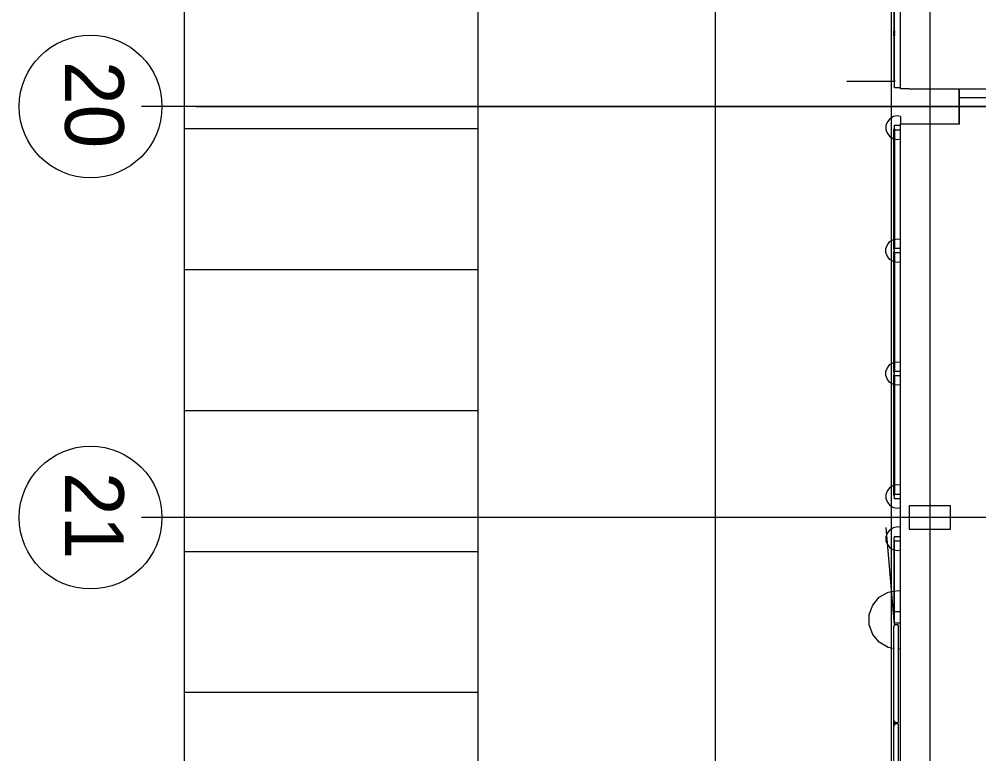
# Model space of a CAD drawing. Extents: x -264165 to -263575, y -1242333 to -1242036.
# Drawn here: x -263923.9 to -263907.56, y -1242220.9 to -1242208.39 of the extents above; entities that cross this region are included whole.
import ezdxf

# ---------------------------------------------------------------- set-up
doc = ezdxf.new("R2010")
doc.units = 0
doc.layers.add('KFA_HESCON_OSI_STAVBY', color=7, linetype='Continuous')
doc.layers.add('KFA_SITUACIA_DRS_VYTYCOVAK_SEDA', color=7, linetype='Continuous')

msp = doc.modelspace()

# ---------------------------------------------------------------- linework, layer by layer
at = {"layer": 'KFA_HESCON_OSI_STAVBY'}
for p, q in [((-263908.393, -1242080.447), (-263908.393, -1242248.737)), ((-263787.486, -1242209.882), (-263921.823, -1242209.882)), ((-263920.885, -1242209.882), (-263905.505, -1242209.882)), ((-263787.486, -1242216.882), (-263921.823, -1242216.882))]:
    msp.add_line(p, q, dxfattribs=at)
for centre in [(-263922.688, -1242209.882), (-263922.688, -1242216.882)]:
    msp.add_circle(centre, 1.216, dxfattribs=at)
at = {"layer": 'KFA_SITUACIA_DRS_VYTYCOVAK_SEDA'}
for p, q in [((-263921.093, -1242087.308), (-263921.093, -1242241.458)), ((-263912.043, -1242228.625), (-263912.043, -1242100.14)), ((-263916.093, -1242187.557), (-263916.093, -1242241.458)), ((-263909.043, -1242227.382), (-263909.043, -1242196.333)), ((-263908.893, -1242209.582), (-263908.893, -1242203.182)), ((-263908.893, -1242209.582), (-263908.893, -1242203.182)), ((-263908.993, -1242209.562), (-263908.993, -1242207.702)), ((-263908.993, -1242209.562), (-263908.993, -1242207.702)), ((-263909.003, -1242207.833), (-263909.003, -1242208.592)), ((-263909.003, -1242207.833), (-263909.003, -1242208.592)), ((-263909.003, -1242208.592), (-263908.993, -1242208.592)), ((-263909.003, -1242208.592), (-263908.993, -1242208.592)), ((-263909.003, -1242208.672), (-263909.003, -1242208.592)), ((-263909.003, -1242208.672), (-263909.003, -1242208.592)), ((-263909.003, -1242208.592), (-263908.993, -1242208.592)), ((-263909.003, -1242208.592), (-263908.993, -1242208.592)), ((-263908.993, -1242208.592), (-263908.993, -1242208.622)), ((-263908.993, -1242208.592), (-263908.993, -1242208.622)), ((-263908.993, -1242208.672), (-263909.003, -1242208.672)), ((-263908.993, -1242208.672), (-263909.003, -1242208.672)), ((-263909.003, -1242208.673), (-263909.003, -1242209.432)), ((-263909.003, -1242208.673), (-263909.003, -1242209.432)), ((-263908.993, -1242208.673), (-263909.003, -1242208.673)), ((-263908.993, -1242208.673), (-263909.003, -1242208.673)), ((-263908.993, -1242208.642), (-263908.993, -1242208.673)), ((-263908.993, -1242208.642), (-263908.993, -1242208.673)), ((-263908.993, -1242209.457), (-263909.808, -1242209.457)), ((-263908.993, -1242209.457), (-263909.808, -1242209.457)), ((-263908.993, -1242209.432), (-263909.003, -1242209.432)), ((-263908.993, -1242209.432), (-263909.003, -1242209.432)), ((-263908.993, -1242209.432), (-263908.993, -1242209.457)), ((-263908.993, -1242209.432), (-263908.993, -1242209.457)), ((-263908.893, -1242209.562), (-263908.993, -1242209.562)), ((-263908.893, -1242209.562), (-263908.993, -1242209.562)), ((-263908.893, -1242209.562), (-263908.893, -1242209.582)), ((-263908.893, -1242209.562), (-263908.893, -1242209.582)), ((-263908.743, -1242209.582), (-263908.893, -1242209.582)), ((-263908.743, -1242209.582), (-263908.893, -1242209.582)), ((-263908.743, -1242209.582), (-263907.893, -1242209.582)), ((-263908.743, -1242209.582), (-263907.893, -1242209.582)), ((-263907.893, -1242210.182), (-263907.893, -1242209.582)), ((-263907.893, -1242210.182), (-263907.893, -1242209.582)), ((-263907.893, -1242209.582), (-263907.893, -1242209.732)), ((-263907.893, -1242209.582), (-263907.893, -1242209.732)), ((-263907.893, -1242209.582), (-263907.368, -1242209.582)), ((-263907.893, -1242209.582), (-263907.368, -1242209.582)), ((-263907.893, -1242209.732), (-263907.893, -1242210.182)), ((-263907.893, -1242209.732), (-263907.893, -1242210.182)), ((-263907.368, -1242209.732), (-263907.893, -1242209.732)), ((-263907.368, -1242209.732), (-263907.893, -1242209.732)), ((-263907.368, -1242209.732), (-263907.893, -1242209.732)), ((-263907.368, -1242209.732), (-263907.893, -1242209.732)), ((-263909.011, -1242210.054), (-263909.071, -1242210.089)), ((-263909.011, -1242210.054), (-263909.071, -1242210.089)), ((-263908.943, -1242210.042), (-263909.011, -1242210.054)), ((-263908.943, -1242210.042), (-263909.011, -1242210.054)), ((-263908.893, -1242210.051), (-263908.943, -1242210.042)), ((-263908.893, -1242210.051), (-263908.943, -1242210.042)), ((-263908.893, -1242210.051), (-263908.893, -1242210.182)), ((-263908.893, -1242210.051), (-263908.893, -1242210.182)), ((-263909.116, -1242210.142), (-263909.14, -1242210.207)), ((-263909.116, -1242210.142), (-263909.14, -1242210.207)), ((-263909.14, -1242210.207), (-263909.14, -1242210.277)), ((-263909.14, -1242210.207), (-263909.14, -1242210.277)), ((-263909.071, -1242210.089), (-263909.116, -1242210.142)), ((-263909.071, -1242210.089), (-263909.116, -1242210.142)), ((-263908.993, -1242210.282), (-263908.993, -1242210.202)), ((-263908.993, -1242210.282), (-263908.993, -1242210.202)), ((-263908.993, -1242210.202), (-263908.893, -1242210.202)), ((-263908.993, -1242210.202), (-263908.893, -1242210.202)), ((-263908.893, -1242216.882), (-263908.893, -1242210.182)), ((-263908.893, -1242216.882), (-263908.893, -1242210.182)), ((-263908.893, -1242216.882), (-263908.893, -1242210.182)), ((-263908.893, -1242216.882), (-263908.893, -1242210.182)), ((-263907.893, -1242210.182), (-263908.893, -1242210.182)), ((-263907.893, -1242210.182), (-263908.893, -1242210.182)), ((-263921.093, -1242210.257), (-263916.093, -1242210.257)), ((-263909.14, -1242210.277), (-263909.116, -1242210.342)), ((-263909.14, -1242210.277), (-263909.116, -1242210.342)), ((-263909.116, -1242210.342), (-263909.071, -1242210.395)), ((-263909.116, -1242210.342), (-263909.071, -1242210.395)), ((-263909.071, -1242210.395), (-263909.011, -1242210.43)), ((-263909.071, -1242210.395), (-263909.011, -1242210.43)), ((-263909.003, -1242212.318), (-263909.003, -1242210.259)), ((-263909.003, -1242212.318), (-263909.003, -1242210.259)), ((-263909.003, -1242210.259), (-263908.993, -1242210.259)), ((-263909.003, -1242210.259), (-263908.993, -1242210.259)), ((-263908.993, -1242210.259), (-263908.993, -1242212.296)), ((-263908.993, -1242210.259), (-263908.993, -1242212.296)), ((-263908.893, -1242210.282), (-263908.993, -1242210.282)), ((-263908.893, -1242210.282), (-263908.993, -1242210.282)), ((-263909.011, -1242210.43), (-263909.003, -1242210.432)), ((-263909.011, -1242210.43), (-263909.003, -1242210.432)), ((-263908.993, -1242210.433), (-263908.943, -1242210.442)), ((-263908.993, -1242210.433), (-263908.943, -1242210.442)), ((-263908.943, -1242210.442), (-263908.893, -1242210.433)), ((-263908.943, -1242210.442), (-263908.893, -1242210.433)), ((-263909.116, -1242212.236), (-263909.071, -1242212.182)), ((-263909.116, -1242212.236), (-263909.071, -1242212.182)), ((-263909.071, -1242212.182), (-263909.011, -1242212.148)), ((-263909.071, -1242212.182), (-263909.011, -1242212.148)), ((-263909.011, -1242212.148), (-263909.003, -1242212.146)), ((-263909.011, -1242212.148), (-263909.003, -1242212.146)), ((-263908.993, -1242212.144), (-263908.943, -1242212.136)), ((-263908.993, -1242212.144), (-263908.943, -1242212.136)), ((-263908.943, -1242212.136), (-263908.893, -1242212.144)), ((-263908.943, -1242212.136), (-263908.893, -1242212.144)), ((-263909.14, -1242212.301), (-263909.116, -1242212.236)), ((-263909.14, -1242212.301), (-263909.116, -1242212.236)), ((-263909.14, -1242212.37), (-263909.14, -1242212.301)), ((-263909.14, -1242212.37), (-263909.14, -1242212.301)), ((-263909.003, -1242212.318), (-263908.993, -1242212.318)), ((-263909.003, -1242212.318), (-263908.993, -1242212.318)), ((-263909.003, -1242214.412), (-263909.003, -1242212.353)), ((-263909.003, -1242214.412), (-263909.003, -1242212.353)), ((-263909.003, -1242212.353), (-263908.993, -1242212.353)), ((-263909.003, -1242212.353), (-263908.993, -1242212.353)), ((-263908.993, -1242212.296), (-263908.893, -1242212.296)), ((-263908.993, -1242212.296), (-263908.893, -1242212.296)), ((-263908.993, -1242212.353), (-263908.993, -1242212.318)), ((-263908.993, -1242212.353), (-263908.993, -1242212.318)), ((-263909.116, -1242212.436), (-263909.14, -1242212.37)), ((-263909.116, -1242212.436), (-263909.14, -1242212.37)), ((-263909.071, -1242212.489), (-263909.116, -1242212.436)), ((-263909.071, -1242212.489), (-263909.116, -1242212.436)), ((-263909.011, -1242212.523), (-263909.071, -1242212.489)), ((-263909.011, -1242212.523), (-263909.071, -1242212.489)), ((-263909.003, -1242212.525), (-263909.011, -1242212.523)), ((-263909.003, -1242212.525), (-263909.011, -1242212.523)), ((-263908.993, -1242212.376), (-263908.993, -1242214.389)), ((-263908.993, -1242212.376), (-263908.993, -1242214.389)), ((-263908.893, -1242212.376), (-263908.993, -1242212.376)), ((-263908.893, -1242212.376), (-263908.993, -1242212.376)), ((-263908.943, -1242212.536), (-263908.993, -1242212.527)), ((-263908.943, -1242212.536), (-263908.993, -1242212.527)), ((-263908.893, -1242212.527), (-263908.943, -1242212.536)), ((-263908.893, -1242212.527), (-263908.943, -1242212.536)), ((-263921.093, -1242212.657), (-263916.093, -1242212.657)), ((-263909.14, -1242214.394), (-263909.116, -1242214.329)), ((-263909.14, -1242214.394), (-263909.116, -1242214.329)), ((-263909.116, -1242214.329), (-263909.071, -1242214.276)), ((-263909.116, -1242214.329), (-263909.071, -1242214.276)), ((-263909.071, -1242214.276), (-263909.011, -1242214.241)), ((-263909.071, -1242214.276), (-263909.011, -1242214.241)), ((-263909.011, -1242214.241), (-263909.003, -1242214.239)), ((-263909.011, -1242214.241), (-263909.003, -1242214.239)), ((-263908.993, -1242214.238), (-263908.943, -1242214.229)), ((-263908.993, -1242214.238), (-263908.943, -1242214.229)), ((-263908.943, -1242214.229), (-263908.893, -1242214.238)), ((-263908.943, -1242214.229), (-263908.893, -1242214.238)), ((-263909.14, -1242214.464), (-263909.14, -1242214.394)), ((-263909.14, -1242214.464), (-263909.14, -1242214.394)), ((-263909.116, -1242214.529), (-263909.14, -1242214.464)), ((-263909.116, -1242214.529), (-263909.14, -1242214.464)), ((-263909.003, -1242214.412), (-263908.993, -1242214.412)), ((-263909.003, -1242214.412), (-263908.993, -1242214.412)), ((-263909.003, -1242216.505), (-263909.003, -1242214.446)), ((-263909.003, -1242216.505), (-263909.003, -1242214.446)), ((-263909.003, -1242214.446), (-263908.993, -1242214.446)), ((-263909.003, -1242214.446), (-263908.993, -1242214.446)), ((-263908.993, -1242214.389), (-263908.893, -1242214.389)), ((-263908.993, -1242214.389), (-263908.893, -1242214.389)), ((-263908.993, -1242214.446), (-263908.993, -1242214.412)), ((-263908.993, -1242214.446), (-263908.993, -1242214.412)), ((-263908.993, -1242214.469), (-263908.993, -1242216.482)), ((-263908.993, -1242214.469), (-263908.993, -1242216.482)), ((-263908.893, -1242214.469), (-263908.993, -1242214.469)), ((-263908.893, -1242214.469), (-263908.993, -1242214.469)), ((-263909.071, -1242214.582), (-263909.116, -1242214.529)), ((-263909.071, -1242214.582), (-263909.116, -1242214.529)), ((-263909.011, -1242214.617), (-263909.071, -1242214.582)), ((-263909.011, -1242214.617), (-263909.071, -1242214.582)), ((-263909.003, -1242214.618), (-263909.011, -1242214.617)), ((-263909.003, -1242214.618), (-263909.011, -1242214.617)), ((-263908.943, -1242214.629), (-263908.993, -1242214.62)), ((-263908.943, -1242214.629), (-263908.993, -1242214.62)), ((-263908.893, -1242214.62), (-263908.943, -1242214.629)), ((-263908.893, -1242214.62), (-263908.943, -1242214.629)), ((-263921.093, -1242215.057), (-263916.093, -1242215.057)), ((-263909.116, -1242216.422), (-263909.14, -1242216.487)), ((-263909.116, -1242216.422), (-263909.14, -1242216.487)), ((-263909.071, -1242216.369), (-263909.116, -1242216.422)), ((-263909.071, -1242216.369), (-263909.116, -1242216.422)), ((-263909.011, -1242216.334), (-263909.071, -1242216.369)), ((-263909.011, -1242216.334), (-263909.071, -1242216.369)), ((-263909.003, -1242216.333), (-263909.011, -1242216.334)), ((-263909.003, -1242216.333), (-263909.011, -1242216.334)), ((-263908.943, -1242216.322), (-263908.993, -1242216.331)), ((-263908.943, -1242216.322), (-263908.993, -1242216.331)), ((-263908.893, -1242216.331), (-263908.943, -1242216.322)), ((-263908.893, -1242216.331), (-263908.943, -1242216.322)), ((-263909.14, -1242216.487), (-263909.14, -1242216.557)), ((-263909.14, -1242216.487), (-263909.14, -1242216.557)), ((-263909.14, -1242216.557), (-263909.116, -1242216.622)), ((-263909.14, -1242216.557), (-263909.116, -1242216.622)), ((-263909.003, -1242216.505), (-263908.993, -1242216.505)), ((-263909.003, -1242216.505), (-263908.993, -1242216.505)), ((-263908.993, -1242216.482), (-263908.893, -1242216.482)), ((-263908.993, -1242216.482), (-263908.893, -1242216.482)), ((-263908.993, -1242216.562), (-263908.993, -1242216.505)), ((-263908.993, -1242216.562), (-263908.993, -1242216.505)), ((-263908.893, -1242216.562), (-263908.993, -1242216.562)), ((-263908.893, -1242216.562), (-263908.993, -1242216.562)), ((-263909.116, -1242216.622), (-263909.071, -1242216.675)), ((-263909.116, -1242216.622), (-263909.071, -1242216.675)), ((-263909.071, -1242216.675), (-263909.011, -1242216.71)), ((-263909.071, -1242216.675), (-263909.011, -1242216.71)), ((-263909.011, -1242216.71), (-263908.943, -1242216.722)), ((-263909.011, -1242216.71), (-263908.943, -1242216.722)), ((-263908.943, -1242216.722), (-263908.893, -1242216.713)), ((-263908.943, -1242216.722), (-263908.893, -1242216.713)), ((-263908.743, -1242216.682), (-263908.743, -1242216.882)), ((-263908.743, -1242216.682), (-263908.743, -1242216.882)), ((-263908.043, -1242216.682), (-263908.743, -1242216.682)), ((-263908.043, -1242216.682), (-263908.743, -1242216.682)), ((-263908.743, -1242216.682), (-263908.743, -1242216.882)), ((-263908.743, -1242216.682), (-263908.743, -1242216.882)), ((-263908.043, -1242216.882), (-263908.043, -1242216.682)), ((-263908.043, -1242216.882), (-263908.043, -1242216.682)), ((-263908.893, -1242223.882), (-263908.893, -1242216.882)), ((-263908.893, -1242223.882), (-263908.893, -1242216.882)), ((-263908.893, -1242226.995), (-263908.893, -1242216.882)), ((-263908.893, -1242226.995), (-263908.893, -1242216.882)), ((-263908.743, -1242216.882), (-263908.743, -1242217.082)), ((-263908.743, -1242216.882), (-263908.743, -1242217.082)), ((-263908.743, -1242216.882), (-263908.743, -1242217.082)), ((-263908.743, -1242216.882), (-263908.743, -1242217.082)), ((-263908.043, -1242217.082), (-263908.043, -1242216.882)), ((-263908.043, -1242217.082), (-263908.043, -1242216.882)), ((-263908.993, -1242218.707), (-263909.138, -1242217.049)), ((-263908.993, -1242218.707), (-263909.138, -1242217.049)), ((-263909.071, -1242217.089), (-263909.116, -1242217.142)), ((-263909.071, -1242217.089), (-263909.116, -1242217.142)), ((-263909.011, -1242217.054), (-263909.071, -1242217.089)), ((-263909.011, -1242217.054), (-263909.071, -1242217.089)), ((-263908.943, -1242217.042), (-263909.011, -1242217.054)), ((-263908.943, -1242217.042), (-263909.011, -1242217.054)), ((-263908.893, -1242217.051), (-263908.943, -1242217.042)), ((-263908.893, -1242217.051), (-263908.943, -1242217.042)), ((-263908.743, -1242217.082), (-263908.043, -1242217.082)), ((-263908.743, -1242217.082), (-263908.043, -1242217.082)), ((-263909.116, -1242217.142), (-263909.14, -1242217.207)), ((-263909.116, -1242217.142), (-263909.14, -1242217.207)), ((-263909.14, -1242217.207), (-263909.14, -1242217.277)), ((-263909.14, -1242217.207), (-263909.14, -1242217.277)), ((-263908.993, -1242217.233), (-263909.003, -1242217.233)), ((-263908.993, -1242217.233), (-263909.003, -1242217.233)), ((-263909.003, -1242217.233), (-263909.003, -1242218.542)), ((-263909.003, -1242217.233), (-263909.003, -1242218.542)), ((-263908.993, -1242217.202), (-263908.893, -1242217.202)), ((-263908.993, -1242217.202), (-263908.893, -1242217.202)), ((-263908.993, -1242217.233), (-263908.993, -1242217.202)), ((-263908.993, -1242217.233), (-263908.993, -1242217.202)), ((-263909.14, -1242217.277), (-263909.116, -1242217.342)), ((-263909.14, -1242217.277), (-263909.116, -1242217.342)), ((-263909.116, -1242217.342), (-263909.071, -1242217.395)), ((-263909.116, -1242217.342), (-263909.071, -1242217.395)), ((-263909.071, -1242217.395), (-263909.011, -1242217.43)), ((-263909.071, -1242217.395), (-263909.011, -1242217.43)), ((-263909.011, -1242217.43), (-263909.003, -1242217.432)), ((-263909.011, -1242217.43), (-263909.003, -1242217.432)), ((-263908.993, -1242218.542), (-263908.993, -1242217.282)), ((-263908.993, -1242218.542), (-263908.993, -1242217.282)), ((-263908.893, -1242217.282), (-263908.993, -1242217.282)), ((-263908.893, -1242217.282), (-263908.993, -1242217.282)), ((-263908.993, -1242217.433), (-263908.943, -1242217.442)), ((-263908.993, -1242217.433), (-263908.943, -1242217.442)), ((-263908.943, -1242217.442), (-263908.893, -1242217.433)), ((-263908.943, -1242217.442), (-263908.893, -1242217.433)), ((-263921.093, -1242217.457), (-263916.093, -1242217.457)), ((-263909.366, -1242218.372), (-263909.254, -1242218.239)), ((-263909.366, -1242218.372), (-263909.254, -1242218.239)), ((-263909.254, -1242218.239), (-263909.104, -1242218.152)), ((-263909.254, -1242218.239), (-263909.104, -1242218.152)), ((-263909.104, -1242218.152), (-263909.003, -1242218.135)), ((-263909.104, -1242218.152), (-263909.003, -1242218.135)), ((-263908.993, -1242218.133), (-263908.933, -1242218.122)), ((-263908.993, -1242218.133), (-263908.933, -1242218.122)), ((-263908.933, -1242218.122), (-263908.893, -1242218.129)), ((-263908.933, -1242218.122), (-263908.893, -1242218.129)), ((-263909.425, -1242218.535), (-263909.366, -1242218.372)), ((-263909.425, -1242218.535), (-263909.366, -1242218.372)), ((-263909.425, -1242218.709), (-263909.425, -1242218.535)), ((-263909.425, -1242218.709), (-263909.425, -1242218.535)), ((-263909.003, -1242218.542), (-263908.993, -1242218.542)), ((-263909.003, -1242218.542), (-263908.993, -1242218.542)), ((-263908.993, -1242218.482), (-263908.893, -1242218.482)), ((-263908.993, -1242218.482), (-263908.893, -1242218.482)), ((-263908.993, -1242218.562), (-263908.993, -1242218.482)), ((-263908.993, -1242218.562), (-263908.993, -1242218.482)), ((-263908.993, -1242218.682), (-263908.993, -1242218.562)), ((-263908.993, -1242218.682), (-263908.993, -1242218.562)), ((-263909.366, -1242218.872), (-263909.425, -1242218.709)), ((-263909.366, -1242218.872), (-263909.425, -1242218.709)), ((-263908.993, -1242218.733), (-263909.003, -1242218.733)), ((-263908.993, -1242218.733), (-263909.003, -1242218.733)), ((-263909.003, -1242220.342), (-263909.003, -1242218.733)), ((-263909.003, -1242220.342), (-263909.003, -1242218.733)), ((-263908.893, -1242218.682), (-263908.993, -1242218.682)), ((-263908.893, -1242218.682), (-263908.993, -1242218.682)), ((-263908.933, -1242218.707), (-263908.993, -1242218.707)), ((-263908.933, -1242218.707), (-263908.993, -1242218.707)), ((-263908.993, -1242218.733), (-263908.993, -1242218.707)), ((-263908.993, -1242218.733), (-263908.993, -1242218.707)), ((-263908.933, -1242218.707), (-263908.933, -1242220.372)), ((-263908.933, -1242218.707), (-263908.933, -1242220.372)), ((-263909.254, -1242219.005), (-263909.366, -1242218.872)), ((-263909.254, -1242219.005), (-263909.366, -1242218.872)), ((-263909.104, -1242219.092), (-263909.254, -1242219.005)), ((-263909.104, -1242219.092), (-263909.254, -1242219.005)), ((-263909.003, -1242219.11), (-263909.104, -1242219.092)), ((-263909.003, -1242219.11), (-263909.104, -1242219.092)), ((-263908.893, -1242219.115), (-263908.933, -1242219.122)), ((-263908.893, -1242219.115), (-263908.933, -1242219.122)), ((-263921.093, -1242219.857), (-263916.093, -1242219.857)), ((-263909.003, -1242220.342), (-263908.993, -1242220.342)), ((-263909.003, -1242220.342), (-263908.993, -1242220.342)), ((-263909.003, -1242220.422), (-263909.003, -1242220.342)), ((-263909.003, -1242220.422), (-263909.003, -1242220.342)), ((-263909.003, -1242220.342), (-263908.993, -1242220.342)), ((-263909.003, -1242220.342), (-263908.993, -1242220.342)), ((-263908.993, -1242220.342), (-263908.993, -1242220.422)), ((-263908.993, -1242220.342), (-263908.993, -1242220.422)), ((-263908.993, -1242220.372), (-263908.993, -1242220.342)), ((-263908.993, -1242220.372), (-263908.993, -1242220.342)), ((-263908.993, -1242220.372), (-263908.933, -1242220.372)), ((-263908.993, -1242220.372), (-263908.933, -1242220.372)), ((-263908.993, -1242220.422), (-263909.003, -1242220.422)), ((-263908.993, -1242220.422), (-263909.003, -1242220.422)), ((-263908.993, -1242220.423), (-263909.003, -1242220.423)), ((-263908.993, -1242220.423), (-263909.003, -1242220.423)), ((-263909.003, -1242222.032), (-263909.003, -1242220.423)), ((-263909.003, -1242222.032), (-263909.003, -1242220.423)), ((-263908.933, -1242220.392), (-263908.993, -1242220.392)), ((-263908.933, -1242220.392), (-263908.993, -1242220.392)), ((-263908.993, -1242220.423), (-263908.993, -1242220.392)), ((-263908.993, -1242220.423), (-263908.993, -1242220.392)), ((-263908.933, -1242220.392), (-263908.933, -1242222.057)), ((-263908.933, -1242220.392), (-263908.933, -1242222.057))]:
    msp.add_line(p, q, dxfattribs=at)

# ---------------------------------------------------------------- texts
at = {"layer": 'KFA_HESCON_OSI_STAVBY'}
for s, p in [('20', (-263923.123, -1242209.105)), ('21', (-263923.123, -1242216.105))]:
    msp.add_text(s, height=1, rotation=270, dxfattribs=at).set_placement(p)

doc.saveas('drawing.dxf')
